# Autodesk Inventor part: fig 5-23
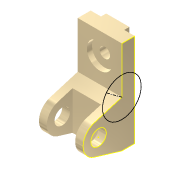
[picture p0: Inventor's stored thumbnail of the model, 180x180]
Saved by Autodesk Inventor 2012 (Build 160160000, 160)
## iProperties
Shininess: 65.0
Angle Display Precision: 2
Document Length Units: 11269
Document Angle Units: 11279
Document Time Units: 11290
Document Mass Units: 11283
Document Length Units Precision: 3
Document Angle Units Precision: 2
Compacted: False
Created: 2001-11
Part Number: fig 5-23
Document SubType Name: Modeling
Designer: Renu Muthoo
Density: 1 g/cm^3
Material: Default
Density: 0.0
Volumn: 0.0
Area: 0.0
PropertySet Name: Model Information
Control State: 0
Master: False
Checked Out: False
Author: Renu Muthoo
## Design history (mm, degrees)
node "Sketch1"
sketch "Sketch2"
  geometry: L1 (33.257, 104.664)-(33.257, -75.336); L2 (33.257, -75.336)-(8.257, -75.336); L3 (8.257, -75.336)-(-45.451, -59.045); L4 (-45.451, -1.628)-(8.257, 14.664); L5 (8.257, 14.664)-(8.257, 104.664); L6 (8.257, 104.664)-(33.257, 104.664); C1 r 15 at (-36.743, -30.336); A1 r 30 centre (-36.743, -30.336) between (-45.451, -1.628) and (-45.451, -59.045)
  constraints: 12 end point, 2 centre point, 2 equal length, 2 parallel, 2 point on circle, 2 tangent, 1 coincident, 1 perpendicular, 1 vertical
  dimensions: "d0" = 180 distance of L1.start L1.end; "d1" = 30 radius of A1; "d2" = 25 distance of L5.end L1.start; "d3" = 45 distance from line of L2 A1.centre; "d4" = 70 distance from line of L1 A1.centre; "d5" = 30 diameter of C1
extrude "Extrusion1" new body sketch "Sketch2" distance "d6" = 85; taper "d7" = 0 deg
workplane "Work Plane1"
sketch "Sketch3"
  geometry: L1 (15, 62.364)-(70, 62.364); L2 (70, 62.364)-(70, -52.386); L3 (70, -52.386)-(15, -52.386); L4 (15, -52.386)-(15, 62.364); L5 (0, -45)-(0, -28.708) reference
  constraints: 8 end point, 2 parallel, 1 horizontal, 1 perpendicular
  dimensions: "d8" = 55 distance of L1.start L1.end; "d9" = 15 distance between parallel lines of L5 L4
extrude "Extrusion2" cut sketch "Sketch3" distance "d10" = 50; taper "d11" = 0 deg
sketch "Sketch4"
  geometry: L1 (0, 25)-(85, 25) reference; L2 (0, 0)-(0, 25) reference; L3 (20, 25)-(65, 25); L4 (65, 25)-(65, 35); L5 (65, 35)-(20, 35); L6 (20, 35)-(20, 25)
  constraints: 8 end point, 2 parallel, 1 horizontal, 1 perpendicular, 1 point on line
  dimensions: "d12" = 45 distance of L4.end L5.end; "d13" = 10 distance of L3.end L4.end; "d14" = 20 distance between parallel lines of L2 L6
extrude "Extrusion3" join sketch "Sketch4" stored distance "d15" = 50; taper "d16" = 0 deg
sketch "Sketch5"
  geometry: L1 (85, 0)-(85, 90) reference; L2 (0, 90)-(85, 90) reference; 1 further point
  dimensions: "d17" = 42 distance from line of L2 point (42.5, 48); "d18" = 42.5 distance from line of L1 point (42.5, 48)
hole "Hole1" sketch "Sketch5" at (42.5, 48) diameter "d19" = 20; stored, may be unused: countersink angle "d23" = 82 deg, drill point angle "d25" = 118 deg; dims "d20" = 6, "d21" = 50, "d22" = 10, "d24" = 8
sketch "Sketch8"
  geometry: L1 (75.336, 33.257)-(75.336, 8.257) reference; L2 (-104.664, 33.257)-(75.336, 33.257) reference; L3 (-104.664, 8.257)-(-104.664, 33.257) reference; L4 (-14.664, 8.257)-(-104.664, 8.257) reference; L5 (1.628, -45.451)-(-14.664, 8.257) reference; L6 (75.336, 8.257)-(59.045, -45.451) reference; C1 r 15 at (30.336, -36.743) reference; C2 r 37.437 at (-14.664, 8.257); A1 r 30 centre (30.336, -36.743) between (1.628, -45.451) and (59.045, -45.451) reference
  constraints: 1 centre point, 1 coincident
sketch "Sketch9"
  geometry: L1 (75.336, 33.257)-(75.336, 8.257) reference; L2 (-14.664, 8.257)-(-104.664, 8.257) reference; L3 (1.628, -45.451)-(-14.664, 8.257) reference; L4 (75.336, 8.257)-(59.045, -45.451) reference; L5 (-14.664, 8.257)-(-37, -21.743); C1 r 15 at (30.336, -36.743) reference; A1 r 30 centre (30.336, -36.743) between (1.628, -45.451) and (59.045, -45.451) reference
  constraints: 2 end point
body "Solid1"
